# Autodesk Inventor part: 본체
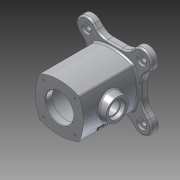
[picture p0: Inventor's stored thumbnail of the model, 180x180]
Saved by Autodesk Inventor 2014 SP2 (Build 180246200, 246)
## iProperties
Created: 2016-05
Part Number: 본체
Material: 알루미늄 6061
Document SubType Name: Modeling
Designer: 달님반
Density: 2.71 g/cm^3
Appearance: 알루미늄 - 평지
Mass: 1114.45 g
Surface Area: 865.594 cm^2
Volume: 411.237 cm^3
Author: 달님반
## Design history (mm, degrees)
sketch "스케치1"
  geometry: L1 (-43, -43)-(43, -43); L2 (43, -43)-(43, 43); L3 (-43, 43)-(-43, -43); L4 (-43, -43)-(43, 43); L5 (43, -43)-(-43, 43); A1 r 85.579 centre (42.579, 0) between (-35.355, 35.355) and (-35.355, -35.355); A2 r 85.579 centre (0, 42.579) between (-35.355, -35.355) and (35.355, -35.355); A3 r 85.579 centre (-42.579, 0) between (35.355, -35.355) and (35.355, 35.355); A4 r 85.579 centre (0, -42.579) between (35.355, 35.355) and (-35.355, 35.355); A5 r 85.579 centre (42.579, 0) between (-35.355, 35.355) and (-35.355, -35.355); A6 r 85.579 centre (0, -42.579) between (35.355, 35.355) and (-35.355, 35.355); A7 r 85.579 centre (-42.579, 0) between (35.355, -35.355) and (35.355, 35.355); A8 r 85.579 centre (0, 42.579) between (-35.355, -35.355) and (35.355, -35.355); 1 further point; 1 other entity
  constraints: 17 point on circle, 10 end point, 8 centre point, 5 tangent, 3 point on line, 2 horizontal, 2 midpoint, 1 parallel, 1 perpendicular, 1 vertical alignment, 20 other
  dimensions: "d0" = 86 distance of L3.start L2.end; "d1" = 86 distance of L2.end L1.end; "d4" = 360 deg dimension on point (0, 0) A1.centre (derived); "d6" = 100 distance of A3.end A1.end; "d81" = 100 distance of A1.start A3.start (derived)
extrude "돌출1" new body sketch "스케치1" distance "d7" = 110; taper "d8" = 0 deg
sketch "스케치2"
  geometry: C1 r 25 at (0, 0); 1 further point
  constraints: 1 centre point, 1 coincident
  dimensions: "d9" = 50 diameter of C1
extrude "돌출2" cut sketch "스케치2" distance "d10" = 12; taper "d11" = 0 deg
sketch "스케치3"
  geometry: C1 r 25 at (0, 0) reference; C2 r 35 at (0, 0)
  constraints: 1 centre point, 1 coincident
  dimensions: "d12" = 70 diameter of C2
extrude "돌출3" cut sketch "스케치3" distance "d13" = 86; taper "d14" = 0 deg
sketch "스케치4"
  geometry: C1 r 25 at (0, 0); 1 further point
  constraints: 1 centre point, 1 coincident
  dimensions: "d15" = 50 diameter of C1
extrude "돌출4" cut sketch "스케치4" stored distance "d16" = 86; taper "d17" = 0 deg
sketch "스케치5"
  geometry: L1 (0, 0)-(49.497, -49.497); L2 (0, 0)-(0, -70); L3 (-49, 49)-(49, 49); L4 (49, 49)-(49, -49); L5 (49, -49)-(-49, -49); L6 (-49, -49)-(-49, 49); L7 (-49, 49)-(49, -49); L8 (49, 49)-(-49, -49); L9 (35.239, -60.483)-(23.755, -49); L10 (60.483, -35.239)-(49, -23.755); L11 (60.483, 35.239)-(49, 23.755); L12 (35.239, 60.483)-(23.755, 49); L13 (-35.239, 60.483)-(-23.755, 49); L14 (-60.483, 35.239)-(-49, 23.755); L15 (-60.483, -35.239)-(-49, -23.755); L16 (-35.239, -60.483)-(-23.755, -49); L17 (49, -23.755)-(49, 23.755); L18 (23.755, 49)-(-23.755, 49); L19 (-49, 23.755)-(-49, -23.755); L20 (-23.755, -49)-(23.755, -49); A1 r 70 centre (0, 0) between (49.497, -49.497) and (0, -70); A2 r 18 centre (49.497, -49.497) between (35.239, -60.483) and (60.483, -35.239); A3 r 18 centre (49.497, 49.497) between (60.483, 35.239) and (35.239, 60.483); A4 r 18 centre (-49.497, 49.497) between (-35.239, 60.483) and (-60.483, 35.239); A5 r 18 centre (-49.497, -49.497) between (-60.483, -35.239) and (-35.239, -60.483); 1 further point
  constraints: 40 end point, 12 point on circle, 5 centre point, 3 parallel, 2 coincident, 2 midpoint, 2 perpendicular, 2 point on line, 1 horizontal, 1 vertical, 33 other
  dimensions: "d18" = 140 diameter of A1; "d19" = 45 deg angle of L1 L2; "d20" = 36 diameter of A2; "d21" = 98 distance of L4.end L5.end; "d22" = 98 distance of L3.end L4.end; "d25" = 360 deg dimension on point (0, 0) L9.start (derived)
extrude "돌출5" join sketch "스케치5" distance "d27" = 12; taper "d28" = 0 deg
sketch "스케치6"
  geometry: C1 r 25 at (0, 0); 1 further point
  constraints: 1 centre point, 1 coincident
  dimensions: "d29" = 50 diameter of C1
extrude "돌출6" cut sketch "스케치6" distance "d30" = 12; taper "d31" = 0 deg
sketch "스케치7"
  geometry: A1 r 18 centre (49.497, -49.497) between (35.239, -60.483) and (60.483, -35.239) reference; A2 r 18 centre (49.497, 49.497) between (60.483, 35.239) and (35.239, 60.483) reference; A3 r 18 centre (-49.497, 49.497) between (-35.239, 60.483) and (-60.483, 35.239) reference; A4 r 18 centre (-49.497, -49.497) between (-60.483, -35.239) and (-35.239, -60.483) reference; 5 further points
  constraints: 4 coincident
hole "구멍1" sketch "스케치7" at (-49.497, 49.497), (49.497, 49.497), (49.497, -49.497), (-49.497, -49.497) diameter "d32" = 10; stored, may be unused: countersink angle "d36" = 90 deg, drill point angle "d38" = 118 deg; dims "d33" = 6, "d34" = 18, "d35" = 4, "d37" = 8
sketch "스케치8"
  geometry: L1 (0, 40)-(0, 0); L2 (0, 0)-(28.284, 28.284); C1 r 25 at (0, 0) reference; A1 r 40 centre (0, 0) between (0, 40) and (28.284, 28.284); 1 further point
  constraints: 4 end point, 2 coincident, 2 point on circle, 1 centre point, 1 vertical
  dimensions: "d39" = 80 diameter of A1; "d40" = 45 deg angle of L1 L2
hole "구멍2" sketch "스케치8" at (28.284, 28.284) diameter "d41" = 3.242; stored, may be unused: countersink angle "d45" = 90 deg, drill point angle "d47" = 118 deg; dims "d42" = 7, "d43" = 18, "d44" = 4, "d46" = 10
node "작업 평면1"
node "작업 평면2"
sketch "스케치10"
  geometry: C1 r 20 at (0, 61); 1 further point
  constraints: 1 centre point, 1 vertical alignment
  dimensions: "d60" = 40 diameter of C1; "d61" = 61 distance of point (0, 0) C1.centre
extrude "돌출7" join sketch "스케치10" stored distance "d62" = 12; taper "d63" = 10 deg
sketch "스케치11"
  geometry: C1 r 20 at (0, 0) reference; 2 further points
  constraints: 1 coincident
hole "구멍3" sketch "스케치11" at (0, 0) diameter "d64" = 25; stored, may be unused: countersink angle "d68" = 90 deg, drill point angle "d70" = 118 deg; dims "d65" = 7, "d66" = 30, "d67" = 8, "d69" = 10
sketch "스케치13"
  geometry: L1 (23.755, -49)-(-23.755, -49) reference; L2 (49, -23.755)-(60.483, -35.239) reference; L3 (49, 23.755)-(49, -23.755) reference; L4 (62.225, -36.77)-(49, -23.544); L5 (36.77, -62.225)-(23.544, -49); L6 (49.497, -49.497)-(0, 0); L7 (49, -23.544)-(23.544, -49); C1 r 5 at (49.497, -49.497) reference; C2 r 25 at (0, 0) reference; C3 r 5 at (49.497, -49.497); A1 r 18 centre (49.497, -49.497) between (35.239, -60.483) and (60.483, -35.239) reference; A2 r 18 centre (49.497, -49.497) between (36.77, -62.225) and (62.225, -36.77)
  constraints: 9 end point, 2 centre point, 2 coincident, 2 concentric, 2 point on circle, 2 point on line, 1 parallel, 1 other
  dimensions: "d82" = 36 distance between parallel lines of L5 L4
extrude "돌출8" join sketch "스케치13" distance "d85" = 12; taper "d86" = 0 deg
fillet "모깎기1" dims "d71" = 25, "d72" = 3
fillet "모깎기2" dims "d73" = 3
chamfer "모따기1" distance "d74" = 1; stored, may be unused: second distance "d75" = 2, angle "d76" = 45 deg
node "작업 평면3"
sketch "스케치12"
  geometry: C1 r 12.5 at (0, 61) reference; 2 further points
  constraints: 1 horizontal alignment, 1 other
  dimensions: "d78" = 29 horizontal distance of point (0, 0) point (-29, 61)
feature "엠보싱1" sketch "스케치12" dims "d0" = 86, "d1" = 86, "d4" = 360 deg (derived), "d6" = 100, "d79" = 0.5, "d80" = 0, "d81" = 100 (derived)
sketch "스케치14"
  geometry: L1 (46, -13.189)-(46, 0) reference; L2 (60.104, -38.891)-(54.201, -32.988) reference; L3 (32.988, -54.201)-(38.891, -60.104) reference; L4 (0, -46)-(13.189, -46) reference; L5 (-46, 0)-(-46, -13.189) reference; L6 (-54.201, -32.988)-(-60.104, -38.891) reference; L7 (-38.891, -60.104)-(-32.988, -54.201) reference; L8 (-13.189, -46)-(0, -46) reference; L9 (13.189, 46)-(0, 46) reference; L10 (38.891, 60.104)-(32.988, 54.201) reference; L11 (54.201, 32.988)-(60.104, 38.891) reference; L12 (46, 0)-(46, 13.189) reference; L13 (-46, 13.189)-(-46, 0) reference; L14 (-60.104, 38.891)-(-54.201, 32.988) reference; L15 (-32.988, 54.201)-(-38.891, 60.104) reference; L16 (0, 46)-(-13.189, 46) reference; C1 r 5 at (49.497, 49.497) reference; C2 r 25 at (0, 0) reference; C3 r 32 at (0, 0) reference; C4 r 5 at (49.497, -49.497) reference; C5 r 5 at (-49.497, 49.497) reference; C6 r 5 at (49.497, 49.497) reference; C7 r 5 at (-49.497, -49.497) reference; C8 r 9 at (-49.497, 49.497); C9 r 9 at (49.497, 49.497); C10 r 9 at (49.497, -49.497); C11 r 9 at (-49.497, -49.497); A1 r 6 centre (33.083, -33.083) between (35.487, -38.581) and (38.581, -35.487) reference; A2 r 88.579 centre (-42.579, 0) between (38.581, -35.487) and (46, 0) reference; A3 r 28 centre (74, -13.189) between (46, -13.189) and (54.201, -32.988) reference; A4 r 15 centre (49.497, -49.497) between (38.891, -60.104) and (60.104, -38.891) reference; A5 r 28 centre (13.189, -74) between (32.988, -54.201) and (13.189, -46) reference; A6 r 88.579 centre (0, 42.579) between (-35.487, -38.581) and (0, -46) reference; A7 r 6 centre (-33.083, -33.083) between (-38.581, -35.487) and (-35.487, -38.581) reference; A8 r 88.579 centre (42.579, 0) between (-46, 0) and (-38.581, -35.487) reference; A9 r 28 centre (-74, -13.189) between (-54.201, -32.988) and (-46, -13.189) reference; A10 r 15 centre (-49.497, -49.497) between (-60.104, -38.891) and (-38.891, -60.104) reference; A11 r 28 centre (-13.189, -74) between (-13.189, -46) and (-32.988, -54.201) reference; A12 r 88.579 centre (0, 42.579) between (0, -46) and (35.487, -38.581) reference; A13 r 88.579 centre (-42.579, 0) between (46, 0) and (38.581, 35.487) reference; A14 r 6 centre (33.083, 33.083) between (38.581, 35.487) and (35.487, 38.581) reference; A15 r 88.579 centre (0, -42.579) between (35.487, 38.581) and (0, 46) reference; A16 r 28 centre (13.189, 74) between (13.189, 46) and (32.988, 54.201) reference; A17 r 15 centre (49.497, 49.497) between (60.104, 38.891) and (38.891, 60.104) reference; A18 r 28 centre (74, 13.189) between (54.201, 32.988) and (46, 13.189) reference; A19 r 88.579 centre (42.579, 0) between (-38.581, 35.487) and (-46, 0) reference; A20 r 28 centre (-74, 13.189) between (-46, 13.189) and (-54.201, 32.988) reference; A21 r 15 centre (-49.497, 49.497) between (-38.891, 60.104) and (-60.104, 38.891) reference; A22 r 28 centre (-13.189, 74) between (-32.988, 54.201) and (-13.189, 46) reference; A23 r 88.579 centre (0, -42.579) between (0, 46) and (-35.487, 38.581) reference; A24 r 6 centre (-33.083, 33.083) between (-35.487, 38.581) and (-38.581, 35.487) reference; 1 further point
  constraints: 4 centre point, 4 coincident
  dimensions: "d90" = 18 diameter of C8; "d91" = 18 diameter of C9; "d92" = 18 diameter of C10; "d93" = 18 diameter of C11
extrude "돌출9" cut sketch "스케치14" distance "d94" = 4; taper "d95" = 0 deg
node "솔리드1"
pattern_circular "원형 패턴1" dims angle "d49" = 360 deg
mirror "대칭1"
pattern_circular "원형 패턴2" dims angle "d88" = 360 deg
node "절단 모서리 투영2"
other parameters: "d59" = -55, "d77" = -113.5
